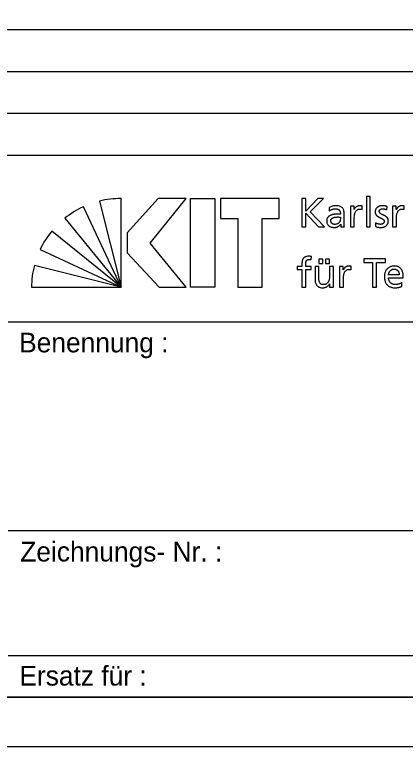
# Model space of a CAD drawing. Extents: x 0 to 841, y 0 to 594.
# Drawn here: x 752.7 to 792.3, y 0 to 74.2 of the extents above; entities that cross this region are included whole.
import ezdxf

# ---------------------------------------------------------------- set-up
doc = ezdxf.new("R2010")
doc.units = 0
doc.layers.add('90_Plankopf', color=7, linetype='Continuous')

msp = doc.modelspace()

# ---------------------------------------------------------------- linework, layer by layer
at = {"layer": '90_Plankopf'}
for p, q in [((658.12, 72.74), (836, 72.74)), ((658.12, 68.49), (836, 68.49)), ((658.12, 64.24), (836, 64.24)), ((658.12, 59.99), (836, 59.99)), ((658.12, 59.99), (836, 59.99)), ((761.275, 55.333), (763.481, 46.586)), ((763.481, 46.586), (763.481, 55.584)), ((781.81, 55.586), (781.81, 52.706)), ((763.481, 46.586), (759.633, 54.752)), ((784.579, 54.662), (784.6, 54.332)), ((787.926, 54.484), (787.926, 54.831)), ((790.457, 54.439), (790.49, 54.778)), ((792.211, 54.484), (792.211, 54.831)), ((757.744, 53.585), (763.481, 46.586)), ((785.73, 53.709), (785.73, 53.523)), ((786.118, 53.118), (786.118, 53.989)), ((789.297, 53.118), (789.277, 52.772)), ((763.481, 46.586), (756.434, 52.286)), ((781.81, 52.706), (782.222, 52.706)), ((783.506, 52.706), (784.108, 52.706)), ((755.24, 50.413), (763.481, 46.586)), ((782.773, 49.393), (782.79, 49.706)), ((763.481, 46.586), (754.658, 48.788)), ((786.827, 48.365), (786.827, 48.712)), ((791.706, 47.841), (790.616, 47.841)), ((790.616, 47.552), (792.119, 47.552)), ((791.958, 46.673), (791.958, 47.061)), ((754.364, 46.586), (763.481, 46.586)), ((752.001, 43.07), (836, 43.07)), ((752.001, 21.92), (836, 21.92)), ((752.001, 9.23), (836, 9.23)), ((836, 5), (658.12, 5)), ((669.8, 5), (836, 5)), ((669.8, 5), (836, 5))]:
    msp.add_line(p, q, dxfattribs=at)
for points in [[(0, 0), (841, 0), (841, 594), (0, 594)], [(25, 589), (836, 589), (836, 5), (25, 5)], [(770.066, 55.586), (767.236, 55.586), (764.073, 52.099), (764.073, 50.092), (767.338, 46.586), (770.085, 46.586), (766.422, 51.063)], [(772.97, 55.586), (772.97, 46.586), (770.501, 46.586), (770.501, 55.586)], [(773.562, 55.586), (773.562, 53.56), (775.301, 53.56), (775.301, 46.586), (777.771, 46.586), (777.771, 53.56), (779.51, 53.56), (779.51, 55.586)]]:
    msp.add_lwpolyline(points, close=True, dxfattribs=at)
for points in [[(788.381, 52.706), (788.768, 52.706), (788.768, 55.801), (788.381, 55.801), (788.381, 52.706)], [(784.108, 52.706), (782.647, 54.224), (784.001, 55.586), (783.452, 55.586), (782.222, 54.319), (782.222, 55.586), (781.81, 55.586)], [(787.122, 54.484), (787.113, 54.484), (787.113, 54.81), (786.75, 54.81), (786.75, 52.706), (787.138, 52.706), (787.138, 53.663)], [(791.407, 54.484), (791.398, 54.484), (791.398, 54.81), (791.035, 54.81), (791.035, 52.706), (791.423, 52.706), (791.423, 53.663)], [(782.222, 52.706), (782.222, 54.117), (783.506, 52.706)], [(785.763, 52.978), (785.772, 52.978), (785.772, 52.706), (786.135, 52.706)], [(783.554, 49.426), (783.554, 49.013), (783.942, 49.013), (783.942, 49.426), (783.554, 49.426)], [(784.231, 49.426), (784.231, 49.013), (784.619, 49.013), (784.619, 49.426), (784.231, 49.426)], [(788.99, 46.586), (789.403, 46.586), (789.403, 49.104), (790.298, 49.104), (790.298, 49.467), (788.094, 49.467), (788.094, 49.104), (788.99, 49.104), (788.99, 46.586)], [(781.824, 48.885), (781.824, 48.691), (781.329, 48.691), (781.329, 48.378), (781.824, 48.378), (781.824, 46.586), (782.212, 46.586), (782.212, 48.378), (782.769, 48.378), (782.769, 48.691), (782.212, 48.691), (782.212, 48.918)], [(783.542, 47.602), (783.542, 48.691), (783.154, 48.691), (783.154, 47.441)], [(785.015, 46.586), (785.015, 48.691), (784.627, 48.691), (784.627, 47.717)], [(786.022, 48.365), (786.014, 48.365), (786.014, 48.691), (785.651, 48.691), (785.651, 46.586), (786.039, 46.586), (786.039, 47.544)], [(784.631, 46.921), (784.639, 46.921), (784.639, 46.586), (785.015, 46.586)]]:
    msp.add_lwpolyline(points, dxfattribs=at)
for centre, start, end in [((763.449, 46.056), 89.80527, 103.18947), ((763.662, 46.118), 115.01261, 128.3968), ((763.816, 46.263), 140.78977, 154.17397), ((763.891, 46.438), 165.72225, 179.10644)]:
    msp.add_arc(centre, 9.528, start, end, dxfattribs=at)
for points in [[(786.118, 53.989), (786.119, 54.18), (786.091, 54.341), (786.033, 54.47), (785.975, 54.599), (785.884, 54.696), (785.759, 54.762), (785.635, 54.827), (785.472, 54.86), (785.272, 54.86), (785.138, 54.859), (785.014, 54.841), (784.898, 54.804), (784.782, 54.768), (784.676, 54.721), (784.579, 54.662)], [(784.6, 54.332), (784.653, 54.376), (784.713, 54.414), (784.779, 54.446), (784.846, 54.478), (784.916, 54.503), (784.99, 54.52), (785.063, 54.538), (785.137, 54.546), (785.21, 54.546), (785.339, 54.546), (785.441, 54.526), (785.518, 54.485), (785.594, 54.444), (785.649, 54.383), (785.682, 54.302), (785.715, 54.219), (785.731, 54.118), (785.73, 53.997)], [(787.926, 54.831), (787.899, 54.837), (787.873, 54.841), (787.849, 54.846), (787.824, 54.85), (787.798, 54.854), (787.769, 54.856), (787.741, 54.859), (787.708, 54.86), (787.67, 54.86), (787.595, 54.859), (787.523, 54.843), (787.452, 54.811), (787.382, 54.779), (787.318, 54.736), (787.261, 54.679), (787.203, 54.623), (787.157, 54.558), (787.122, 54.484)], [(787.138, 53.663), (787.139, 53.84), (787.163, 53.993), (787.21, 54.121), (787.257, 54.249), (787.323, 54.348), (787.409, 54.416), (787.494, 54.486), (787.595, 54.521), (787.712, 54.521), (787.746, 54.522), (787.78, 54.519), (787.818, 54.514), (787.855, 54.509), (787.891, 54.499), (787.926, 54.484)], [(790.49, 54.778), (790.414, 54.801), (790.337, 54.82), (790.259, 54.836), (790.181, 54.851), (790.097, 54.859), (790.007, 54.86), (789.903, 54.86), (789.805, 54.847), (789.716, 54.82), (789.625, 54.794), (789.547, 54.753), (789.48, 54.7), (789.412, 54.647), (789.359, 54.579), (789.322, 54.498), (789.284, 54.417), (789.265, 54.321), (789.264, 54.212), (789.265, 54.128), (789.282, 54.056), (789.315, 53.994), (789.347, 53.933), (789.391, 53.88), (789.445, 53.834), (789.5, 53.79), (789.559, 53.75), (789.623, 53.715), (789.688, 53.68), (789.753, 53.647), (789.817, 53.617), (789.882, 53.586), (789.942, 53.555), (789.995, 53.522), (790.05, 53.49), (790.093, 53.454), (790.126, 53.413), (790.158, 53.373), (790.176, 53.325), (790.176, 53.271), (790.176, 53.215), (790.163, 53.167), (790.139, 53.128), (790.116, 53.09), (790.084, 53.059), (790.045, 53.035), (790.006, 53.012), (789.963, 52.995), (789.917, 52.985), (789.871, 52.975), (789.825, 52.97), (789.78, 52.97), (789.742, 52.97), (789.695, 52.975), (789.639, 52.986), (789.584, 52.997), (789.526, 53.014), (789.466, 53.036), (789.405, 53.058), (789.35, 53.085), (789.297, 53.118)], [(789.277, 52.772), (789.366, 52.726), (789.46, 52.694), (789.558, 52.678), (789.656, 52.662), (789.755, 52.655), (789.854, 52.656), (789.949, 52.656), (790.04, 52.669), (790.127, 52.695), (790.215, 52.722), (790.293, 52.762), (790.363, 52.816), (790.431, 52.869), (790.487, 52.938), (790.527, 53.02), (790.568, 53.103), (790.588, 53.2), (790.589, 53.312), (790.588, 53.408), (790.571, 53.489), (790.539, 53.556), (790.506, 53.622), (790.462, 53.679), (790.408, 53.726), (790.354, 53.772), (790.295, 53.811), (790.23, 53.845), (790.165, 53.878), (790.101, 53.909), (790.036, 53.937), (789.971, 53.966), (789.912, 53.995), (789.858, 54.026), (789.804, 54.058), (789.76, 54.095), (789.727, 54.136), (789.695, 54.179), (789.678, 54.23), (789.677, 54.291), (789.678, 54.348), (789.696, 54.396), (789.729, 54.434), (789.763, 54.472), (789.808, 54.5), (789.864, 54.519), (789.92, 54.538), (789.982, 54.546), (790.048, 54.546), (790.072, 54.546), (790.102, 54.543), (790.139, 54.538), (790.175, 54.531), (790.213, 54.523), (790.254, 54.513), (790.295, 54.503), (790.333, 54.491), (790.369, 54.478), (790.405, 54.466), (790.434, 54.453), (790.457, 54.439)], [(792.211, 54.831), (792.184, 54.837), (792.158, 54.841), (792.134, 54.846), (792.11, 54.85), (792.083, 54.854), (792.054, 54.856), (792.026, 54.859), (791.993, 54.86), (791.955, 54.86), (791.88, 54.859), (791.808, 54.843), (791.737, 54.811), (791.667, 54.779), (791.603, 54.736), (791.546, 54.679), (791.488, 54.623), (791.442, 54.558), (791.407, 54.484)], [(791.423, 53.663), (791.424, 53.84), (791.448, 53.993), (791.495, 54.121), (791.542, 54.249), (791.608, 54.348), (791.694, 54.416), (791.779, 54.486), (791.88, 54.521), (791.997, 54.521), (792.03, 54.522), (792.065, 54.519), (792.103, 54.514), (792.14, 54.509), (792.175, 54.499), (792.211, 54.484)], [(785.73, 53.997), (785.68, 54), (785.633, 54.002), (785.589, 54.003), (785.546, 54.004), (785.502, 54.005), (785.459, 54.006), (785.415, 54.006), (785.368, 54.006), (785.318, 54.006), (785.237, 54.006), (785.151, 53.999), (785.063, 53.984), (784.973, 53.97), (784.886, 53.947), (784.801, 53.914), (784.715, 53.881), (784.638, 53.838), (784.569, 53.785), (784.499, 53.731), (784.444, 53.665), (784.403, 53.588), (784.362, 53.509), (784.341, 53.418), (784.34, 53.312), (784.341, 53.16), (784.374, 53.035), (784.439, 52.939), (784.504, 52.842), (784.594, 52.77), (784.71, 52.724), (784.825, 52.679), (784.959, 52.656), (785.111, 52.656), (785.2, 52.657), (785.28, 52.668), (785.35, 52.689), (785.421, 52.709), (785.483, 52.736), (785.536, 52.769), (785.59, 52.802), (785.635, 52.837), (785.673, 52.874), (785.71, 52.911), (785.741, 52.945), (785.763, 52.978)], [(785.73, 53.523), (785.73, 53.418), (785.708, 53.323), (785.664, 53.24), (785.62, 53.157), (785.554, 53.092), (785.467, 53.043), (785.38, 52.995), (785.272, 52.97), (785.144, 52.97), (785.1, 52.97), (785.054, 52.978), (785.008, 52.992), (784.963, 53.007), (784.92, 53.028), (784.882, 53.057), (784.843, 53.087), (784.812, 53.123), (784.789, 53.165), (784.765, 53.207), (784.753, 53.257), (784.752, 53.312), (784.754, 53.386), (784.772, 53.448), (784.808, 53.497), (784.844, 53.546), (784.891, 53.586), (784.949, 53.615), (785.007, 53.645), (785.069, 53.667), (785.135, 53.682), (785.201, 53.696), (785.265, 53.706), (785.326, 53.711), (785.387, 53.715), (785.439, 53.717), (785.483, 53.717), (785.524, 53.717), (785.565, 53.715), (785.607, 53.713), (785.648, 53.711), (785.689, 53.709), (785.73, 53.709)], [(786.135, 52.706), (786.132, 52.726), (786.129, 52.753), (786.126, 52.787), (786.125, 52.821), (786.122, 52.865), (786.121, 52.919), (786.119, 52.973), (786.118, 53.039), (786.118, 53.118)], [(782.79, 49.706), (782.751, 49.712), (782.71, 49.719), (782.668, 49.723), (782.625, 49.728), (782.579, 49.731), (782.53, 49.731), (782.388, 49.73), (782.27, 49.71), (782.178, 49.671), (782.086, 49.631), (782.014, 49.574), (781.962, 49.5), (781.91, 49.426), (781.875, 49.337), (781.854, 49.233), (781.833, 49.129), (781.824, 49.014), (781.824, 48.885)], [(782.212, 48.918), (782.212, 48.99), (782.216, 49.056), (782.224, 49.116), (782.232, 49.177), (782.249, 49.23), (782.275, 49.275), (782.3, 49.32), (782.338, 49.355), (782.388, 49.379), (782.439, 49.404), (782.505, 49.417), (782.588, 49.417), (782.621, 49.417), (782.655, 49.415), (782.688, 49.411), (782.722, 49.407), (782.75, 49.401), (782.773, 49.393)], [(786.827, 48.712), (786.8, 48.717), (786.774, 48.722), (786.75, 48.727), (786.725, 48.731), (786.698, 48.734), (786.67, 48.737), (786.642, 48.739), (786.609, 48.74), (786.571, 48.74), (786.496, 48.74), (786.423, 48.724), (786.352, 48.692), (786.282, 48.66), (786.218, 48.616), (786.161, 48.56), (786.104, 48.503), (786.057, 48.439), (786.022, 48.365)], [(786.039, 47.544), (786.039, 47.721), (786.064, 47.873), (786.11, 48.001), (786.158, 48.129), (786.224, 48.228), (786.31, 48.297), (786.395, 48.367), (786.496, 48.401), (786.612, 48.402), (786.646, 48.403), (786.681, 48.4), (786.718, 48.395), (786.756, 48.389), (786.791, 48.379), (786.827, 48.365)], [(792.119, 47.552), (792.119, 47.722), (792.103, 47.88), (792.072, 48.023), (792.041, 48.168), (791.989, 48.293), (791.918, 48.4), (791.846, 48.507), (791.751, 48.591), (791.631, 48.65), (791.512, 48.709), (791.365, 48.74), (791.19, 48.74), (791.041, 48.74), (790.906, 48.714), (790.785, 48.662), (790.665, 48.61), (790.561, 48.537), (790.474, 48.442), (790.387, 48.347), (790.321, 48.235), (790.275, 48.105), (790.228, 47.976), (790.205, 47.833), (790.204, 47.676), (790.204, 47.504), (790.225, 47.348), (790.269, 47.209), (790.312, 47.069), (790.379, 46.95), (790.469, 46.85), (790.558, 46.749), (790.671, 46.672), (790.808, 46.619), (790.945, 46.564), (791.107, 46.538), (791.293, 46.537), (791.408, 46.538), (791.506, 46.545), (791.587, 46.56), (791.667, 46.575), (791.737, 46.593), (791.797, 46.614), (791.855, 46.634), (791.909, 46.654), (791.958, 46.673)], [(790.616, 47.841), (790.623, 47.91), (790.639, 47.978), (790.664, 48.047), (790.688, 48.116), (790.722, 48.179), (790.768, 48.236), (790.812, 48.294), (790.869, 48.339), (790.937, 48.374), (791.006, 48.408), (791.087, 48.426), (791.182, 48.427), (791.266, 48.426), (791.34, 48.411), (791.404, 48.381), (791.47, 48.35), (791.524, 48.309), (791.569, 48.255), (791.614, 48.201), (791.648, 48.139), (791.671, 48.069), (791.694, 47.998), (791.706, 47.922), (791.706, 47.841)], [(784.627, 47.717), (784.627, 47.589), (784.615, 47.471), (784.589, 47.365), (784.564, 47.26), (784.525, 47.169), (784.473, 47.092), (784.421, 47.015), (784.354, 46.956), (784.273, 46.914), (784.193, 46.872), (784.097, 46.851), (783.987, 46.85), (783.875, 46.857), (783.786, 46.889), (783.721, 46.945), (783.656, 47.002), (783.61, 47.084), (783.582, 47.193), (783.554, 47.302), (783.541, 47.438), (783.542, 47.602)], [(791.958, 47.061), (791.933, 47.041), (791.899, 47.019), (791.852, 46.995), (791.806, 46.971), (791.754, 46.948), (791.694, 46.926), (791.634, 46.904), (791.572, 46.886), (791.506, 46.872), (791.44, 46.858), (791.374, 46.851), (791.309, 46.85), (791.217, 46.851), (791.13, 46.868), (791.046, 46.902), (790.964, 46.935), (790.889, 46.983), (790.825, 47.045), (790.761, 47.107), (790.71, 47.181), (790.673, 47.267), (790.636, 47.353), (790.617, 47.448), (790.616, 47.552)], [(783.154, 47.441), (783.154, 47.251), (783.181, 47.09), (783.237, 46.955), (783.293, 46.82), (783.379, 46.717), (783.496, 46.645), (783.612, 46.574), (783.761, 46.538), (783.942, 46.537), (784.04, 46.538), (784.135, 46.553), (784.225, 46.583), (784.315, 46.614), (784.396, 46.658), (784.466, 46.715), (784.537, 46.772), (784.592, 46.841), (784.631, 46.921)]]:
    msp.add_open_spline(points, degree=3, dxfattribs=at)

# ---------------------------------------------------------------- texts
for s, p in [('Benennung :', (753.113, 39.979)), ('Zeichnungs- Nr. :', (753.227, 18.758)), ('Ersatz für :', (753.139, 6.169))]:
    msp.add_text(s, height=2, dxfattribs=at).set_placement(p)

doc.saveas('drawing.dxf')
